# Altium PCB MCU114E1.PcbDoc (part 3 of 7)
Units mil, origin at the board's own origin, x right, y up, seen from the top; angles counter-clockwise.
Board outline 4163.97 x 2322.49 mil, 8 copper layers (Top Layer, GND 2, Signal Layer 3, Power 4, Power 5, Signal Layer 6, GND 7, Bottom), stack 61.2 mil thick; 444 components, 416 nets, 1812 pads, 989 vias.
Unrouted connection lines stored in the file: 3.
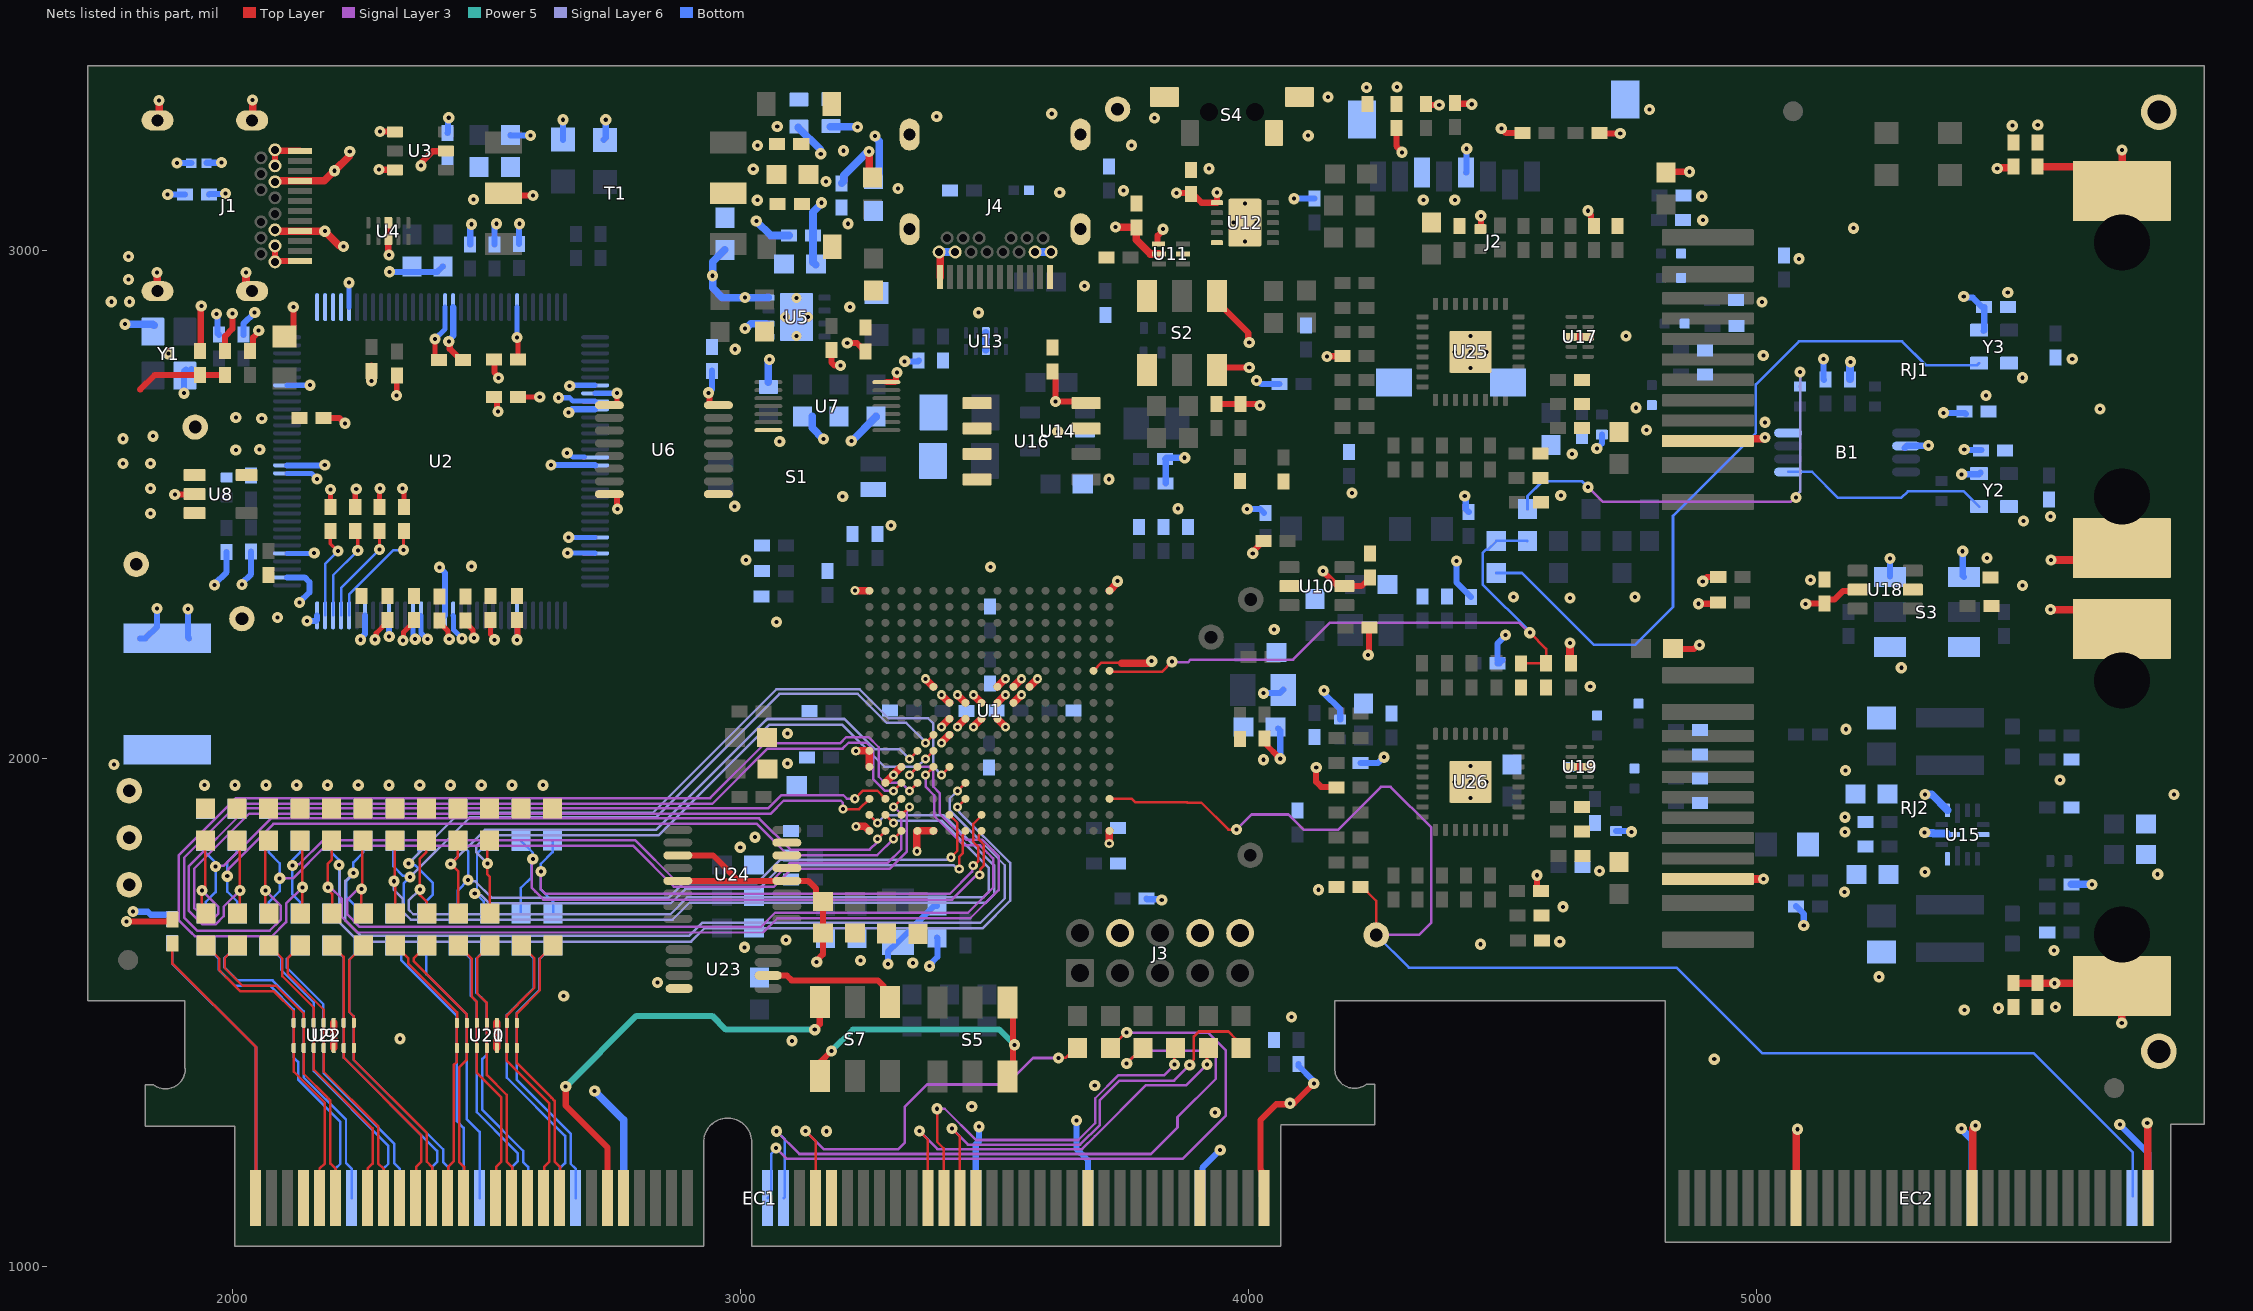
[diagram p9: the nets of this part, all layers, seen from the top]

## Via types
v1: diameter 22, hole 8, Top Layer to Bottom, tented both sides, 818 vias
v2: diameter 18, hole 8, Top Layer to Bottom, tented both sides, 153 vias
v3: diameter 19.68, hole 7.87, Top Layer to Bottom, 18 vias

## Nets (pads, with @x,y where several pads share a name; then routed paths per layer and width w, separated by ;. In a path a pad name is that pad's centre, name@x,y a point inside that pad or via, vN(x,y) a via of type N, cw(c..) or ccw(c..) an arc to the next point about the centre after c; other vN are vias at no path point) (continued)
3V3: B1.6 C31.1 C35.1 C36.1 C37.1 C40.2 C43.1 C64.1 C66.1 C86.2 C103.1 C152.1 C153.1 EC1.119 J2.4 J3.10 L3.1 L4.1 R1.2 R2.2 R34.1 R35.1 R36.2 R37.2 R39.2 R40.2 R42.2 R46.1 R51.2 R54.2 R71.2 R73.1 R88.2 R89.2 R105.2 R106.2 R107.2 R108.1 R111.2 R130.2 R131.1 R133.2 R134.2 R135.1 R137.2 R138.1 R142.1 R145.2 R151.2 R166.1 R168.2 R169.1 R194.2 R202.2 R204.2 R205.1 S2.1 S2.4 S3.1 S3.4 TP8.1 U6.16 U7.14 U10.5 U11.1 U12.1 U16.8 U18.5 Y2.4 Y3.4 | length 3588.3
  Top Layer w12: v1(1792,1680) 1872.2,1680 R204.2@1876.08,1683.88 ; v1(2937,2720) 2938.91,2718.09 2938.91,2697.42 2940.64,2695.69 U6.16@2956.44,2695.69 ; R1.2@3178.87,2800.13 3178.87,2779.69 3184.56,2774 v1(3197,2774) ; v1@3211,2818 3228.87,2818 C35.1@3245.68,2801.19 ; U7.14@3287.01,2740.93 3304.17,2740.93 3306.23,2742.99 3306.23,2758.67 v1(3307.83,2760.27) ; C86.2@3614,2761.57 3619.6,2755.96 v1(3619.6,2703.23) 3676.33,2703.23 U16.8@3679.87,2699.69 ; U11.1@3820.83,3014.5 3820.83,3029.13 3831,3039.29 v1(3831,3042) ; v1(3858,3113) 3888.38,3113 3907.32,3094.06 U12.1@3937.32,3094.06 3937.83,3094.57 v1(3937.83,3114.27) ; R54.2@3936.87,2698.31 R51.2@3983.87,2698.31 4018.69,2698.31 v1(4022,2695) v1@4023.31,2696.31 ; S2.4@3937.9,2765.17 3942.73,2770 v1(4001,2770) ; S2.1@3937.9,2910.83 3937.9,2899.02 3999.09,2837.83 3999.09,2820.91 v1(4001,2819) ; v1(4007.83,2404.27) 4007.83,2407.27 R39.2@4029.25,2428.69 ; EC1.119@4029.8,1135.27 4024.98,1140.09 4024.98,1189.44 4023,1191.42 4023,1289 4054.09,1320.09 4079.09,1320.09 v1(4081,1322) 4089,1322 v1(4128,1361) ; R46.1@4031,2039.38 4031,2031 v1(4062,2000) ; v1(4132.84,1982.84) 4132.67,1982.67 4132.67,1954.61 4142.6,1944.68 4172.26,1944.68 R142.1@4172.26,1942.8 ; v1(4145.83,2369.27) 4175.41,2339.69 U10.5@4188.01,2339.69 4221.87,2339.69 C37.1@4238.83,2356.65 ; v1(4153.83,2791.27) 4154.54,2791.98 4183.58,2791.98 R108.1@4184.29,2791.27 ; v1(4235,2204) 4236.45,2205.45 4236.45,2256.55 R40.2@4237.9,2258 ; C36.1@4290.4,3240.27 4290.4,3205.3 4301.83,3193.86 v1(4301.83,3193.27) ; R36.2@4348.51,3288.31 4350.55,3286.27 v1(4374.83,3286.27) ; R37.2@4406.83,3290.27 4408.23,3288.87 4437.77,3288.87 v1(4438.79,3287.85) ; R134.2@4455.83,3041.95 4456.67,3042.8 v1(4456.67,3068.27) ; v1(4497,3240) 4506,3231 R111.2@4538.38,3231 ; v1(4566.87,1770.69) 4566.87,1742.69 R151.2@4571.87,1737.69 ; v1(4667.83,3078.27) 4667.83,3075.56 4673.82,3069.57 4673.82,3051.9 R107.2@4677.83,3047.89 ; R89.2@4690.62,3231 4691.62,3230 v1(4731,3230) ; R135.1@4821.39,3153.32 4823.07,3155 v1(4867,3155) ; R169.1@4834.33,2217.27 4835.6,2216 4876.29,2216 4884.29,2224 v1(4887,2224) ; v1(4885,2305) 4920.57,2305 R138.1@4923.25,2307.69 ; v1(4893.28,2349.13) 4901.62,2357.48 R137.2@4923.6,2357.48 ; v1(5095.87,2304.69) 5096.87,2305.69 C103.1@5131.87,2305.69 ; C103.1@5132.44,2305.06 5132.44,2307.85 5138.25,2313.66 5152.85,2313.66 5169.2,2330.01 5196.2,2330.01 U18.5@5199.87,2333.69
  Bottom w12: v1(1804.5,1699.5) 1805,1699 1833.5,1699 1839.5,1693 1870.27,1693 1876.08,1687.19 R205.1@1876.08,1683.88 ; v1(2937,2720) 2944,2727 C31.1@2944,2763.38 ; v1(3290,1596) 3290,1620.27 3309,1639.27 L4.1@3309.83,1639.27 3381.33,1710.76 C66.1@3386.53,1710.76 ; v1(3323,2782) 3349.28,2782 R71.2@3350.58,2783.3 ; R202.2@3798.49,1724.69 3799.7,1723.48 3827.62,1723.48 v1(3828.83,1722.27) ; R105.2@3836.62,2542 3836.62,2589 R106.2@3835.62,2590 3837.82,2592.2 v1(3873.9,2592.2) ; v1(3996.87,2491.27) 4022.29,2491.27 R34.1@4030.06,2483.5 ; v1(4015.29,2744) 4018,2744 4025,2737 R88.2@4060.38,2737 ; v1(4029,2129) 4061.19,2129 L3.1@4067.87,2135.69 ; C64.1@4057.6,2059.54 4062,2055.14 v1(4062,2000) ; v1(4089,3102) 4128.38,3102 R194.2@4129,3102.62 ; R42.2@4098,1399.38 4098,1395.44 4126.09,1367.35 4126.09,1362.91 v1(4128,1361) ; v1(4148,2134) 4148,2129 4179.99,2097.01 R168.2@4179.99,2077.06 ; R130.2@4219.5,1991.68 4254.68,1991.68 v1(4266,2003) ; v1(4409,2389) 4409,2346.62 R145.2@4437,2318.62 ; v1(4425,2517) 4425,2514.29 4427.06,2512.23 4427.06,2491.12 R35.1@4432.87,2485.31 ; J2.4@4427.45,3153.27 4428.14,3153.96 4428.14,3199.58 v1(4428.83,3200.27) ; R133.2@4489.3,2187.89 4493.24,2187.89 4499.05,2193.7 4489.3,2193.7 4489.3,2226.59 4505,2242.29 v1(4505,2243.65) ; v1(4684.83,2610.27) 4694.83,2620.27 R131.1@4694.83,2637.58 ; R166.1@4722.83,1857.58 4751.52,1857.58 v1(4752.83,1856.27) ; R2.2@5077.15,1709.69 5092,1694.84 v1(5092,1672) ; v1(5130.87,2786.69) 5130.87,2746.69 R73.1@5131.87,2745.69 ; S3.4@5261.83,2358.64 v1(5261.83,2394.27) ; B1.6@5290.87,2611.69 5295.06,2615.87 5337.44,2615.87 v1(5337.83,2616.27) ; v1(5366.87,2680.69) 5408.87,2680.69 C43.1@5410.87,2678.69 ; v1(5402.87,2559.69) 5436.87,2559.69 Y2.4@5439.87,2562.69 ; v1(5404.83,2408.27) 5404.83,2360.02 S3.1@5407.27,2357.58 ; v1(5406.83,2909.27) 5408.74,2907.36 5424.58,2907.36 5443.25,2888.69 C153.1@5447.19,2888.69 ; v1(5407.83,2608.27) 5408.62,2607.48 5441.66,2607.48 C152.1@5441.87,2607.69 ; Y3.4@5445.87,2841.69 5447.19,2843 C153.1@5447.19,2887.69
  other v1: 3210.02,2818
5V0: C51.1 C53.1 C54.1 R20.2 R21.2 R28.2 R29.2 R53.2 R93.1 R99.2 R103.2 TP9.1 U11.2 U15.7 U15.11 | length 335.2
  Top Layer w15: v1@3738,3045.38 v1(3738,3046) 3738.25,3045.75 C51.1@3778.81,3045.75 3778.81,3020.93 3806.47,2993.27 U11.2@3823.17,2993.27
  Bottom w15: R20.2@3054.73,2740.93 3054.73,2783.65 v1(3056.88,2785.8) ; v1(3218,2624.98) 3219.01,2624.98 3266.55,2672.52 R21.2@3266.55,2673.5 ; v1(5330.83,1929.69) 5343.64,1929.69 U15.11@5374.91,1898.42 ; R103.2@5618.44,1752.69 v1(5659.44,1752.69)
  other v1: 5330.83,1777.27 5820.44,1929.69 3769,3207
20MHZ_CLK: R70.1 Y3.3 | length 1437.9
  Bottom w5.2: R70.1@4487,2365.5 4537.5,2365.5 4679,2224 4760,2224 4834.83,2298.83 4834.83,2477.83 4997.83,2640.83 4997.83,2736.27 5082.83,2821.27 5285.83,2821.27 5332.83,2774.27 5433.13,2774.27 Y3.3@5437.07,2778.21
25MHZ_CLK: B1.1 Y2.3 | length 414.8
  Bottom w5: B1.1@5061.29,2564.3 5108.8,2564.3 5159.83,2513.27 5283.83,2513.27 5296.83,2526.27 5407.01,2526.27 Y2.3@5437.07,2496.21
ADC_3V0_REF: S7.6 U23.6 | length 272.3
  Top Layer w12: U23.6@3054.43,1573.47 3091.2,1573.47 3100.83,1563.84 3270.19,1563.84 3280.81,1553.22 3280.81,1535.03 S7.6@3294.49,1521.35
ADC_REF: C123.1 R57.2 U24.3 U24.5 U24.12 | length 574
  Top Layer w12: U24.5@2876.55,1759.77 2995.83,1759.77 ; U24.3@2876.55,1809.77 2945.83,1809.77 2995.83,1759.77 ; v1(3149.83,1600.27) 3149.83,1602.97 3162.1,1615.24 C123.1@3162.1,1657.51 R57.2@3162.1,1719.51 3161.11,1719.51 3148.41,1732.21 3148.41,1744.9 3133.55,1759.77 U24.12@3091.11,1759.77 2995.83,1759.77
DEBUG_ID4: R3.1 U2.63 | length 183.1
  Top Layer w6.25: R3.1@2192.85,2448.01 2192.85,2422.89 2207.05,2408.69 v1(2207.87,2408.69)
  Bottom w5: U2.63@2182.5,2282.11 2182.5,2383.31 v1(2207.87,2408.69)
DEBUG_ID5: R4.1 U2.62 | length 193.1
  Top Layer w6.25: R4.1@2241.87,2448.06 2246.87,2443.06 v1(2246.87,2409.69)
  Bottom w5: U2.62@2198.25,2282.11 2198.25,2361.06 v1(2246.87,2409.69) ; v1@2248.37,2408.19 v1@2251.87,2411.69
DEBUG_ID6: R5.1 U2.61 | length 197.4
  Top Layer w6.25: v1(2289.87,2411.69) R5.1@2289.87,2448.06
  Bottom w5: U2.61@2214,2282.11 2214,2335.81 v1(2289.87,2411.69)
DEBUG_ID7: R6.1 U2.60 | length 222.5
  Top Layer w6.25: v1(2336.87,2410.69) 2336.87,2447.06 R6.1@2337.87,2448.06
  Bottom w5: U2.60@2229.74,2282.11 2229.74,2323.56 2316.87,2410.69 v1(2336.87,2410.69)
EMU_0: EC1.2 R205.2 | length 567
  Bottom w5: R205.2@1881.64,1637.31 1881.64,1597.36 2046.62,1432.38 EC1.2@2046.62,1138.69
EMU_1: EC1.1 R204.1 | length 566.1
  Top Layer w5: R204.1@1882,1636.63 1882,1597 2046.62,1432.38 2046.62,1282.29 EC1.1@2046.62,1138.69
EMU_3V3: C2.1 C3.1 C4.1 C5.1 C6.1 C7.1 C8.1 C9.1 C17.1 C30.1 R3.2 R4.2 R5.2 R6.2 R7.1 R10.2 R13.2 R14.1 TP2.1 U2.7 U2.8 U2.9 U2.16 U2.26 U2.28 U2.39 U2.47 U2.51 U2.52 U2.69 U2.79 U2.90 U2.101 U2.113 U2.122 U6.1 U8.5 | length 1528.1
  Top Layer w10: R3.2@2192.85,2495.26 v1(2192.87,2529.69) ; R4.2@2241.87,2495.31 2241.87,2528.69 v1(2243.87,2530.69) ; v1(2280.83,2234.27) 2283.13,2236.56 2283.13,2246.92 2305.09,2268.89 C7.1@2305.09,2272.82 ; R5.2@2289.87,2495.31 2289.87,2530.69 v1(2290.87,2531.69) ; v1(2323,2715) 2323.5,2715.5 2323.5,2753.88 R7.1@2324,2754.38 ; v1(2334.87,2531.69) 2337.87,2528.69 R6.2@2337.87,2495.31 ; v1(2335.98,2232.42) 2337.13,2233.56 2337.13,2249.33 2349.06,2261.27 2349.48,2261.27 2357.09,2268.89 C6.1@2357.09,2272.82 ; v1(2398.87,2825.69) 2398.87,2792.06 C9.1@2406.25,2784.69 ; C5.1@2408.09,2271.82 2408.09,2267.89 2424.54,2251.44 2424.54,2237.56 v1(2426.83,2235.27) ; C4.1@2459.09,2271.82 2459.09,2267.89 2473.54,2253.44 2473.54,2239.56 v1(2475.83,2237.27) ; C3.1@2508.09,2272.82 2508.09,2244.72 2519.09,2233.72 v1@2519.09,2233.07 ; v1(2559.87,2828.69) 2562.49,2826.06 C8.1@2562.49,2785.69 C8.1@2563.25,2786.44 ; C30.1@2560.87,2711.69 v1(2604.87,2711.69) ; U6.1@2741.87,2695.69 2754.18,2695.69 2756.83,2698.34 v1(2756.83,2719.27)
  Top Layer w12: R14.1@2034.87,2802.31 2040.68,2808.12 2040.68,2828.79 2051.87,2839.98 v1(2051.87,2842.69) ; C2.1@2560.09,2272.82 2561.09,2271.82 v1@2561.09,2234.44
  Bottom w10: U2.69@2107.7,2404.16 2160.18,2404.16 v1(2161.09,2405.07) ; U2.79@2107.7,2561.64 2155.92,2561.64 v1(2166.87,2550.69) ; U2.90@2107.7,2734.86 2107.8,2734.97 2152.99,2734.97 v1(2153.09,2735.07) ; U2.101@2229.74,2888.41 2229.74,2936.56 v1(2229.87,2936.69) ; U2.52@2355.73,2282.11 2355.73,2239.37 v1(2359.83,2235.27) ; U2.51@2371.48,2282.11 2371.48,2247.62 v1(2383.83,2235.27) ; v1@2397.87,2824.69 v1(2398.87,2825.69) 2418.72,2845.53 U2.113@2418.72,2888.41 ; U2.47@2434.47,2282.11 2435.53,2281.05 2435.53,2253.46 2451.83,2237.16 v1(2451.83,2236.27) ; v1(2559.87,2828.69) 2560.45,2829.27 U2.122@2560.45,2888.41 ; v1@2560.09,2233.07 2560.45,2233.42 U2.39@2560.45,2282.11 ; v1(2641.85,2710.32) 2663.7,2710.32 2670.4,2703.62 2714,2703.62 U2.9@2714,2703.37 ; v1(2658.87,2601.69) 2661.58,2601.69 2669.94,2593.32 U2.16@2692.44,2593.32 ; v1(2659.87,2404.69) 2713.47,2404.69 U2.28@2714,2404.16 ; v1(2661.87,2435.69) U2.26@2713.98,2435.67 ; v1(2663.83,2733.27) 2665.43,2734.86 U2.7@2714,2734.86 ; U2.8@2714,2719.12 2714.07,2719.19 2756.76,2719.19 v1(2756.83,2719.27)
  other v1: 2516.09,2234.07 2560.09,2234.07 2006.87,2607.69 2053.87,2608.69 2057.87,2669.69 2006.87,2671.69
EMU_GND: C1.2 C2.2 C3.2 C4.2 C5.2 C6.2 C7.2 C8.2 C9.2 C10.2 C11.2 C12.2 C13.2 C14.2 C15.2 C16.2 C17.2 C18.2 C19.2 C20.2 C21.1 C22.2 C30.2 C34.2 D2.1 D8.2 D13.2 J1.A1 J1.A12 J1.B1 J1.B12 J1.M1 J1.M2 J1.S1 J1.S2 J1.S3 J1.S4 R11.1 R12.1 R15.1 R16.1 R17.2 TP3.1 U2.10 U2.17 U2.48 U2.55 U2.58 U2.64 U2.66 U2.80 U2.114 U3.4 U3.6 U4.3@2306.85,3021.82 U4.8@2306.85,3054.7 U6.8 U8.2 Y1.2 Y1.4 | length 2515.9
  Top Layer w12: v1(1886.87,2519.69) 1887.37,2520.19 1925.37,2520.19 U8.2@1926.87,2521.69 ; C18.2@1936.87,2802.31 1937.94,2803.37 1937.94,2889.94 v1(1939,2891) ; C16.2@1985.87,2802.31 1985.87,2831.69 2000,2845.81 v1(2000,2876) ; J1.M1@2083.93,3009.26 J1.B1@2083.93,2977.76 2085.9,2979.73 J1.A12@2133.54,2979.73 ; J1.M2@2083.93,3166.74 J1.B12@2083.93,3198.24 2085.9,3196.27 J1.A1@2133.54,3196.27 ; D2.1@2102.87,2831.02 2104.35,2831.02 2120,2846.68 v1(2120,2889) ; C17.2@2179.49,2670.69 2210.35,2670.69 2221.04,2660 v1(2222,2660) ; v1(2273.87,2743.69) C1.2@2273.87,2773.69 ; v1(2288.83,3159.27) 2289.13,3158.97 2319.6,3158.97 U3.6@2319.9,3158.66 ; v1(2290.83,3234.27) 2291.23,3233.87 2319.5,3233.87 U3.4@2319.9,3233.47 ; U4.8@2306.85,3054.7 U4.3@2306.85,3021.82 2306.85,2992.31 v1(2308.09,2991.07) ; v1(2426,2821) 2427.91,2819.09 2427.91,2806.33 2449.56,2784.69 C9.2@2453.49,2784.69 ; C30.2@2515.25,2713.69 2520.92,2708.02 2520.92,2685.18 v1(2522.83,2683.27) ; C8.2@2515.25,2785.69 2515.87,2785.06 2515.87,2759.93 2523.83,2751.97 v1(2523.83,2749.27) ; U6.8@2741.87,2520.69 2755.48,2520.69 2757.21,2518.95 2757.21,2492.35 v1(2757.87,2491.69)
  Top Layer w15: v1(1852,2957) 1852,2920.72 J1.S3@1852.83,2919.89 ; J1.S2@1852.83,3256.11 1856,3259.28 v1(1856,3295) ; v1(2027,2957) 2027,2931.94 J1.S4@2039.05,2919.89 ; J1.S1@2039.05,3256.11 2040,3257.06 v1(2040,3296)
  Bottom w12: C34.2@1818.87,2236.69 1828.87,2236.69 1851.87,2259.69 v1(1851.87,2295.69) ; v1(1872.83,3110.27) 1872.93,3110.17 1906.37,3110.17 R15.1@1906.47,3110.07 ; v1(1890.83,3172.27) 1890.93,3172.17 1919.19,3172.17 C20.2@1919.29,3172.07 ; v1(1904.64,2719.27) 1904.64,2762.08 Y1.4@1908.83,2766.27 ; v1(1912.87,2294.69) 1912.87,2238.69 C34.2@1914.87,2236.69 ; Y1.4@1914.04,2761.05 Y1.4@1919.37,2766.38 ; v1(1964.87,2341.69) 1964.87,2343.18 1988.87,2367.18 C15.2@1988.87,2407.06 ; v1(1969,2875) 1970.91,2873.09 1970.91,2837.27 C14.2@1973.87,2834.31 ; v1(2018.87,2342.69) 2018.87,2345.39 2036.87,2363.39 R11.1@2036.87,2407.44 ; C13.2@2021.87,2834.31 2021.87,2855.87 v1(2044,2878) ; U2.66@2107.7,2356.91 2142.19,2356.91 2151.83,2347.27 2151.83,2327.64 v1(2131.87,2307.69) ; U2.80@2107.7,2577.38 2181.57,2577.38 v1(2181.87,2577.69) ; v1(2146.83,2271.27) 2164.69,2271.27 2166.75,2273.33 U2.64@2166.75,2282.11 ; v1(2252.33,2234.07) 2252.33,2236.88 2261.24,2245.78 U2.58@2261.24,2282.11 ; U2.55@2308.48,2282.11 2308.66,2281.94 v1(2308.66,2240.44) ; v1(2309.09,2958.07) 2403.59,2958.07 R17.2@2414.09,2968.57 ; v1(2407.53,2376.69) 2418.72,2365.5 U2.48@2418.72,2282.11 ; C22.2@2423.63,3231.17 2424.73,3232.28 2424.73,3260.17 v1(2425.83,3261.27) ; v1(2426,2821) 2426,2823.71 2434.73,2832.44 2434.73,2888.14 U2.114@2434.47,2888.41 ; C11.2@2468.09,3011.69 2468.09,3048.91 v1(2470.87,3051.69) ; C12.2@2516.09,3011.69 2516.09,3048.91 v1(2519.87,3052.69) ; C21.1@2547.09,3226.94 2547.77,3226.27 v1(2586.83,3226.27) ; C10.2@2564.09,3012.69 2564.09,3051.91 v1(2564.87,3052.69) ; v1(2626.83,2578.27) 2627.27,2577.83 2713.55,2577.83 U2.17@2714,2577.38 ; D8.2@2650.87,3218.02 2650.83,3218.07 v1(2650.83,3257.27) ; v1(2661.83,2681.27) 2668.18,2687.62 U2.10@2714,2687.62 ; D13.2@2730.87,3218.02 2734.83,3221.98 v1(2734.83,3257.27)
  Bottom w15: v1(1789,2855) 1843.72,2855 Y1.2@1845.84,2852.88
  other v1: 2088.87,2277.69 2470.87,2378.69
EMU_USB_5V0: C16.1 C18.1 C20.1 C21.2 C22.1 J1.A4 J1.A9 J1.B4 J1.B9 R15.2 R18.2 T1.5 TP1.1 U3.2 U8.1 U8.3 | length 692.2
  Top Layer w12: 1818.87,2726.69 1847.25,2755.06 C18.1@1936.87,2755.06 C16.1@1985.87,2755.06 ; v1(2201,3157) v1@2202,3158 ; v1@2368.86,3170.17 2372,3170.17 2373.36,3171.53 2373.36,3174.67 2394.08,3195.39 2419.61,3195.39 U3.2@2420.29,3196.07 ; T1.5@2533.61,3112.69 2538.03,3108.27 v1(2591.83,3108.27)
  Top Layer w15: J1.B4@2083.93,3040.76 2086.53,3038.16 2096.14,3038.16 2096.29,3038 2133.54,3038 v1(2182,3038) 2210.66,3009.34 2217.66,3009.34 v1(2219,3008) ; J1.B9@2083.93,3135.24 2085.9,3137.21 J1.A4@2133.54,3137.21 2181.21,3137.21 v1(2201,3157) ; v1@2202,3158 2229.66,3185.66 2229.66,3193.66 v1(2231,3195)
  Bottom w12: C20.1@1949.09,3172.07 1949.7,3172.67 1978.23,3172.67 v1(1978.83,3173.27) ; R15.2@1953.72,3110.07 1954.82,3111.17 1985.73,3111.17 v1(1986.83,3112.27)
  other v1: 1838.87,2482.69 1838.87,2531.69 1784.87,2580.69 1838.87,2580.69 1784.87,2629.69 1843.87,2634.69 1874,2797 1761.83,2899.27 1797.83,2899.27 1795.83,2943.27 1795.83,2988.27 2474.83,3100.27 2371.45,3166.91
ERRORSTS: EC2.178 R38.2 TP4.1 U1.P16 | length 2921.4
  Top Layer w5: U1.P16@3726.04,1921.06 3770.21,1921.06 3777.34,1913.94 3878.79,1913.94 3878.96,1913.77 3906.48,1913.77 3959.74,1860.52 v1(3975.88,1860.52) ; R38.2@4218.95,1752.27 4250.83,1720.39 TP4.1@4250.83,1653.27
  Signal Layer 3 w5: v1(3975.88,1860.52) 4005.63,1890.27 4078.04,1890.27 4108.3,1860 4175.29,1860 4260.06,1944.77 4279.08,1944.77 4359.3,1864.55 4359.3,1677.73 4334.83,1653.27 TP4.1@4250.83,1653.27
  Bottom w5: TP4.1@4250.83,1653.27 4315.1,1589 4842.01,1589 5010.25,1420.77 5544.23,1420.77 5739.14,1225.86 EC2.178@5739.14,1138.98
ETH1_EARTH: C101.2 C117.2 pad.6 R136.2 R170.2 RJ1.10 RJ1.13 RJ1.14 RJ2.10 RJ2.13 RJ2.14 | length 1047.5
  Top Layer w15: RJ2.10@4903.31,1763.48 5012.62,1763.48 v1(5012.83,1763.27) ; RJ1.10@4903.31,2625.13 4907.81,2629.64 5011.75,2629.64 5014.11,2632 v1(5016,2632) ; v1(5472.83,3161.27) 5474.17,3162.61 5501.98,3162.61 C101.2@5504.44,3165.06 ; C117.2@5504.44,1558.31 R170.2@5552.44,1558.31 v1(5585.83,1558.27) ; R136.2@5552.44,3165.06 RJ1.13@5669.68,3165.06 ; v1(5577.44,2293.43) 5679.66,2293.43 RJ2.13@5717.87,2255.21 ; v1(5578.44,2390.94) 5694.31,2390.94 RJ1.14@5717.87,2414.5 ; v1(5585.83,1558.27) 5707.64,1558.27 5717.83,1548.07 v1(5717.83,1480.27) ; RJ1.13@5717.87,3116.87 5718.44,3117.43 v1(5718.44,3197.69)
F28P65x_25MHZ_CLK: R65.2 R75.2 | length 865.8
  Signal Layer 3 w5: v1(4667.83,2534.27) 4696.65,2505.45 5065.57,2505.45 5074.12,2514 v1(5077,2514)
  Signal Layer 6 w5: v1(5077,2514) 5077,2517.6 5084.83,2525.43 v1(5084.83,2761.27)
  Bottom w5.2: R75.2@4548.44,2491.17 4548.56,2491.29 4548.56,2516.56 4578,2546 4656.1,2546 v1(4667.83,2534.27) ; R65.2@5084.44,2732.53 5084.83,2732.92 v1(5084.83,2761.27)
F28P65x_CLK: C126.1 R41.2 R70.2 R75.1 U1.F16 | length 1293.3
  Top Layer w5: U1.F16@3726.04,2173.03 3728.1,2170.97 3828.97,2170.97 v1(3849,2191) ; C126.1@4536,2187.62 4584.73,2187.62 R41.2@4585,2187.89 4585,2216 v1(4553,2248)
  Signal Layer 3 w5: v1(3849,2191) 3850.23,2189.77 3880.08,2189.77 3885.48,2195.17 4087.25,2195.17 4160.09,2268 4531.57,2268 4551.57,2248 v1(4553,2248)
  Bottom w5: R75.1@4548.44,2428.17 4548.11,2428.5 R70.2@4487,2428.5 4487,2427.51 4470.8,2411.31 4466.66,2411.31 4460.8,2405.45 4460.8,2342.2 4553,2250 v1(4553,2248)
GND: B1.4 C23.2 C24.2 C25.2 C26.2 C27.2 C28.2 C29.2 C31.2 C32.2 C33.2 C34.1 C35.2 C36.2 C37.2 C38.2 C39.2 C40.1 C41.2 C42.2 C43.2 C44.2 C45.2 C46.2 C47.2 C49.2 C51.2 C52.2 C53.2 C54.2 C55.2 C56.2 C57.2 C58.2 C59.2 C60.2 C61.2 C62.2 C63.2 C64.2 C65.2 C66.2 C67.2 C68.2 C69.2 C70.2 C71.2 C72.2 C73.2 C74.2 C75.2 C76.2 C77.2 C78.2 C79.2 C80.2 C81.2 C82.2 C83.2 C84.2 C85.2 C86.1 C87.1 C88.1 C89.2 C90.2 C91.2 C92.2 C93.2 C94.2 C95.1 C96.1 C97.2 C98.2 C99.2 C100.2 C101.1 C102.1 C103.2 C104.1 C105.2 C106.2 C107.2 C108.2 C109.2 C110.2 C111.1 C112.1 C113.2 C114.1 C115.2 C116.1 C117.1 C118.2 C119.2 C120.2 C121.2 C122.2 C123.2 C124.2 C125.2 C126.2 C128.2 C129.2 C130.2 C131.2 C132.2 C133.2 C134.2 C135.2 C136.2 C137.2 C138.2 C139.2 C140.2 C141.2 C142.2 C143.2 C144.2 C145.2 C146.2 C147.2 C148.2 C149.2 C150.2 C151.2 C152.2 C153.2 D7.1 D9.1 EC1.7 EC1.10 EC1.19 EC1.22 EC1.35 EC1.38 EC1.46 EC1.47 EC1.65 EC1.83 EC1.97 EC1.111 EC2.135 EC2.157 EC2.179 J2.6 J2.S1 J2.S2 J2.S3 J2.S4 J3.4 J3.8 J4.A1 J4.A12 J4.B1 J4.B12 J4.M1 J4.M2 J4.S1 J4.S2 J4.S3 J4.S4 R22.1 R23.1 R25.1 R26.1 R27.1 R31.1 R32.2 R38.1 R41.1 R43.1 R48.2 R69.1 R72.1 R74.2 R76.1 R77.1 R95.1 R104.1 R109.1 R112.1 R113.1 R123.1 R124.1 R125.1 R127.1 R128.1 R129.1 R132.1 R136.1 R139.2 R140.2 R141.2 R143.1 R146.1 R147.1 R159.1 R160.1 R161.1 R162.1 R163.2 R167.1 R170.1 R171.1 R206.1 S1.4 S2.3 S2.6 S3.3 S3.6 S4.1 S4.2 S4.3 T1.2 TP14.1 U1.A1 U1.A16 U1.F15 U1.G5 U1.G9 U1.G10 U1.G11 U1.H6 U1.H7 U1.H8 U1.H9 U1.H10 U1.J6 U1.J7 U1.J8 U1.J9 U1.K6 U1.L1 U1.M1 U1.M3 U1.N2 U1.T1 U1.T4 U1.T5 U1.T16 U5.5 U5.9@3110.34,2868.99 U6.9 U7.7 U9.5 U9.10 U10.2 U11.5 U12.5 U12.11 U13.3@3482.69,2805.13 U13.8@3482.69,2838 U14.2 U15.2 U15.9 U16.1 U16.2 U16.3 U16.4 U16.7 U17.3@4634.86,2830.21 U17.8@4667.74,2830.21 U18.2 U19.3@4634.86,1984.21 U19.8@4667.74,1984.21 U20.5 U20.10 U21.5 U21.10 U22.5 U22.10 U23.4 U24.13 U24.14 U24.15 U25.33@4436.44,2800.69 U26.33@4436.44,1954.69 Y2.2 Y3.2 | length 1781.7
  Top Layer w5: U1.F15@3694.54,2173.03 3710.52,2189 3750.17,2189 3751.63,2190.46
  Top Layer w15: U9.5@2199.56,1431.08 U9.10@2199.56,1480.29 ; U20.5@2520.56,1431.08 U20.10@2520.56,1480.29 ; v2(3225.5,2330.98) 3225.83,2330.65 3253.46,2330.65 U1.A1@3253.6,2330.51 ; v2(3226.84,2015.32) 3227.07,2015.55 U1.L1@3253.6,2015.55 U1.M1@3253.6,1984.05 ; v2(3227,1867) 3244.66,1867 U1.T1@3253.6,1858.07 ; U1.N2@3285.09,1952.55 v2(3300.84,1968.3) U1.M3@3316.59,1984.05 ; v2(3347,1818) 3347,1856.98 U1.T4@3348.09,1858.07 U1.T5@3379.58,1858.07 ; v2(3363.83,2157.28) U1.G5@3379.58,2141.53 ; J4.B1@3390.76,2997.07 3392.73,2995.1 J4.A12@3392.73,2947.46 ; v2@3394.16,2062.6 3395.14,2062.6 U1.J6@3411.08,2078.54 ; v2(3395.33,2031.29) U1.K6@3411.08,2047.04 ; v2(3395.33,2125.78) U1.H6@3411.08,2110.03 ; v2@3425.65,2062.6 3426.63,2062.6 U1.J7@3442.57,2078.54 ; v2(3426.83,2125.78) U1.H7@3442.57,2110.03 ; v2@3457.15,2062.6 3458.13,2062.6 U1.J8@3474.07,2078.54 ; v2(3458.32,2125.78) U1.H8@3474.07,2110.03 ; U1.J9@3505.57,2078.54 v2(3521.31,2062.79) ; U1.H9@3505.57,2110.03 v2(3521.31,2125.78) ; U1.G9@3505.57,2141.53 v2(3521.31,2157.28) ; U1.H10@3537.06,2110.03 v2(3552.81,2125.78) ; U1.G10@3537.06,2141.53 v2(3552.81,2157.28) ; U1.G11@3568.56,2141.53 v2(3584.31,2157.28) ; v2(3725.44,1832.95) 3725.44,1857.47 U1.T16@3726.04,1858.07 ; U1.A16@3726.04,2330.51 3726.04,2330.71 3740.32,2344.99 3740.32,2348.06 v1(3741.66,2349.39) ; 3750.17,2187.67 3804.67,2187.67 v1(3809,2192) ; v1(4632,2228) 4632,2189.72 R143.1@4633.83,2187.89 ; U19.3@4634.86,1984.21 U19.8@4667.74,1984.21 ; U17.3@4634.86,2830.21 U17.8@4667.74,2830.21 ; EC2.135@5076.95,1135.27 5076.95,1267.95 v1(5080,1271) ; EC2.157@5423.41,1135.27 5424.54,1136.4 5424.54,1272.54 v1(5430,1278) ; v1(5768,1283) 5768.93,1282.07 5768.93,1136.2 EC2.179@5769.87,1135.27
  Bottom w12: v1(3371.56,1591.75) 3371.56,1594.09 3387.56,1610.09 3387.56,1646.74 C66.2@3386.53,1647.77
  Bottom w15: v1(3031,3058) 3059.31,3029.69 C29.2@3095.25,3029.69 ; 3140.78,2673.5 3140.78,2651.22 v1(3163,2629) ; J4.B1@3390.76,2997.07 J4.M1@3422.26,2997.07 ; U13.3@3482.69,2805.13 U13.8@3482.69,2838 ; J4.M2@3579.74,2997.07 J4.B12@3611.24,2997.07 ; R74.2@5183,2746.62 5183,2780 v1(5184,2781) ; v1(5330,1855) 5331.08,1853.92 5346.29,1853.92 5347.26,1852.95 5373.14,1852.95 U15.9@5375.4,1850.69
  other v1: 3169,1267 3934,1304 3455,1316 3697,1357 4916,1408.86 3101,1445 2330,1449 4084,1492 5408,1505.86 5475,1509 5587.44,1511.69 2652,1533 2836.44,1559.69 5240.27,1570.95 3339,1598 3236,1603 5584.44,1622.69 3008,1629 4456,1635 4612,1640 3089.27,1643.42 4618.44,1708.69 5172.44,1737.69 4137.44,1742.24 5788.44,1772.69 4690,1779 2999.44,1825.69 3028.44,1845.69 5173,1856 5173,1885 1945,1948 2005.55,1948 2066.09,1948 2126.64,1948 2187.18,1948 2247.73,1948 2308.27,1948 2368.82,1948 2429.36,1948 2489.91,1948 2550.45,1948 2611,1948 5596,1958 5174.44,1976.69 1767,1988.75 3092.44,1990.69 4029,1998 3092.44,2049.69 5175,2058 4672,2142 5284,2179 4050,2254 3071,2269 4632,2316 4521,2318 4760,2318 5522.44,2340.69 5105.44,2351.69 3492,2377 3011,2391 5452.44,2394.69 3295.77,2458.95 5524.44,2467.69 5577.44,2476.69 3861,2492 2988.44,2496.69 3201,2516 4614,2518 4203,2523 3725,2550 4636.44,2599.69 3077,2624 3624.31,2644 4782.44,2646.69 5016,2662 5675,2688 4762.1,2690.64 5450.44,2714.69 5522.44,2749.69 5620.44,2786.69 5012.44,2793.69 2989.44,2805.69 4742,2832 3468.28,2877.64 3215,2889 5010.07,2898.78 5493.44,2917.69 3677,2930 5082.44,2983.69 5190,3044 3211.44,3052.69 4893.44,3059.69 3033,3099 4343.44,3099.69 4405.44,3099.69 4891.44,3106.69 3628,3114 3753.44,3117.69 3310,3122 3025,3160 3922,3161 3033.44,3206.69 4117,3226 3072.27,3243.95 5502.44,3245.69 5552.44,3246.69 3814.44,3260.69 3386,3264 3612.34,3269.11 4788.44,3277.69 4156,3302 4231.44,3320.69 4291.44,3321.69
  other v2: 3395.33,2062.79 3426.83,2062.79 3458.32,2062.79
  other v3: 4436.44,1923.19 4404.94,1954.69 4436.44,1954.69 4467.93,1954.69 4436.44,1986.18 4436.44,2769.19 4404.94,2800.69 4436.44,2800.69 4467.93,2800.69 3110.34,2831.59 4436.44,2832.18 3087.7,2868.99 3132.97,2868.99 3110.34,2906.39 3992.44,3017.28 3969.8,3054.69 4015.07,3054.69 3992.44,3092.09
HSEC_5V0: C27.1 C28.1 EC1.48 EC1.84 EC1.98 EC1.112 EC2.158 EC2.180 R22.2 R24.2 R28.1 TP11.1 U5.8 | length 1437
  Top Layer w15: v1(3252.96,3194.58) 3252.96,3150.54 R24.2@3260,3143.5
  Bottom w12: EC1.84@3462.87,1139.75 3462.87,1241 3468.87,1247 3468.87,1275.87 v1(3469,1276) ; v1(3661,1288) 3660.83,1287.83 3660.83,1232.95 3683.35,1210.43 EC1.98@3683.35,1135.27 ; EC1.112@3903.82,1135.27 3908.65,1140.09 3908.65,1195.08 v1(3943.83,1230.27) ; v1(5714,1280) 5738.34,1255.66 5769.87,1224.13 EC2.180@5769.87,1139.76
  Bottom w15: v1(2713,1346) 2769.96,1289.04 EC1.48@2769.96,1135.27 ; R22.2@2969,3001.5 2945.04,2977.55 v1(2945.04,2950.42) 2945.04,2926.52 2964.29,2907.27 v1(3009.02,2907.27) U5.8@3053.75,2907.27 ; U5.8@3053.75,2907.69 U5.8@3054.87,2907.69 ; R28.1@3176.83,3243.77 3177.08,3243.52 3229.58,3243.52 v1(3229.83,3243.27) ; C27.1@3198.87,3132.31 3203.18,3136.62 3203.18,3147.62 v1@3246.83,3191.27 ; C28.1@3261.87,3141.18 3273.07,3152.38 3273.07,3215.13 3264.83,3223.37 v1(3264.83,3225.27) ; v1@5401.83,1272.27 5423.41,1250.69 EC2.158@5423.41,1135.27
  other v1: 5402.04,1272.27
HSEC_ADC-VREFHI: EC1.45 S7.4 | length 871.6
  Top Layer w12: v1(2656,1355) 2656,1317.36 2724.18,1249.18 2738.46,1234.89 EC1.45@2738.46,1135.27 ; v1(3146,1466.91) 3146,1467.82 3155.83,1477.65 3155.83,1520.48 S7.4@3156.7,1521.35
  Power 5 w12: v1(2656,1355) 2795,1494 2944,1494 2971.09,1466.91 v1(3146,1466.91)
HSEC_ADC_A0A1_N: EC1.11 R176.2 U9.2 U9.13 | length 636.9
  Top Layer w4.9: R176.2@2010.13,1632.95 1985.08,1607.91 1985.08,1588.5 2002.81,1570.78 2020.59,1553 2086.45,1553 2140.5,1498.95 U9.13@2140.5,1480.29 2140.5,1380.1 2186.34,1334.26 2186.34,1334.19 2189.79,1330.74 2189.79,1330.67 2192.9,1327.56 2192.9,1203.52 2203.03,1193.39 EC1.11@2203.03,1135.27
HSEC_ADC_A0A1_P: EC1.9 R175.2 U9.1 U9.14 | length 637.6
  Top Layer w4.9: R175.2@1948.04,1632.95 1974.18,1606.81 1974.18,1583.99 1977.2,1580.97 1977.2,1580.83 1995.03,1563 1995.17,1563 2016.07,1542.1 2081.94,1542.1 2120.82,1503.22 U9.14@2120.82,1480.29 U9.1@2120.82,1431.08 2120.82,1384.3 2132.79,1372.32 2132.79,1372.25 2182,1323.04 2182,1203.85 2171.54,1193.39 EC1.9@2171.54,1135.27
HSEC_ADC_A2A3_N: EC1.17 R178.2 U9.4 U9.11 | length 586.1
  Top Layer w4.9: R178.2@2134.31,1632.95 2109.17,1607.82 2109.17,1576.83 2179.87,1506.13 U9.4@2179.87,1431.08 2179.87,1396.41 2179.87,1384.13 2287,1277 2287,1203.91 2297.52,1193.39 EC1.17@2297.52,1135.27
HSEC_ADC_A2A3_P: EC1.15 R177.2 U9.3 U9.12 | length 586.3
  Top Layer w4.9: R177.2@2072.04,1632.95 2098.27,1606.72 2098.27,1572.31 2160.19,1510.4 U9.3@2160.19,1431.08 2160.19,1388.26 2276,1272.44 2276,1203.36 2266.02,1193.39 EC1.15@2266.02,1135.27
HSEC_ADC_A4A5_N: EC1.23 R180.2 U9.7 U9.8 | length 572.5
  Top Layer w4.9: R180.2@2258.49,1631.97 2230.14,1603.62 2230.14,1501.92 2238.67,1493.39 2238.67,1480.55 U9.8@2238.93,1480.29 U9.7@2238.93,1431.08 2238.93,1407.49 2382.9,1263.52 2382.9,1207.03 2393.08,1196.85 EC1.23@2393.08,1138.69
HSEC_ADC_A4A5_P: EC1.21 R179.2 U9.6 U9.9 | length 571.3
  Top Layer w4.9: R179.2@2196.4,1632.95 2219.24,1610.11 U9.9@2219.24,1480.29 U9.6@2219.24,1431.08 2219.24,1411.76 2372,1259 2372,1207.27 2361.58,1196.85 EC1.21@2361.58,1138.69
HSEC_ADC_A8A9_N: EC1.36 R182.2 U21.4 U21.11 | length 554.5
  Bottom w4.9: R182.2@2505.87,1632.33 2505.87,1631.35 2489.62,1615.1 2488.64,1615.1 2480,1606.46 2480,1540 2489.74,1530.26 2500.62,1519.39 2500.62,1480.55 U21.4@2500.87,1480.29 U21.11@2500.87,1431.08 2500.87,1418.24 2492.09,1409.45 2492.09,1308.87 2572.31,1228.65 2572.31,1206.55 2582.05,1196.8 EC1.36@2582.05,1138.69
HSEC_ADC_A8A9_P: EC1.34 R181.2 U21.3 U21.12 | length 546.9
  Bottom w4.9: R181.2@2443.78,1632.33 2443.78,1631.35 2469.1,1606.03 2469.1,1533.79 2481.19,1521.7 U21.3@2481.19,1480.29 U21.12@2481.19,1431.08 2481.19,1304.36 2550.19,1235.36 2561.41,1224.14 2561.41,1207.65 2550.56,1196.8 EC1.34@2550.56,1138.69
HSEC_ADC_A10A11_N: EC1.42 R184.2 U21.7 U21.8 | length 575
  Bottom w4.9: R184.2@2631.04,1632.95 2604.4,1606.31 2604.4,1544.95 2559.93,1500.48 U21.7@2559.93,1480.29 U21.8@2559.93,1431.08 2559.93,1368.07 2665.73,1262.27 2665.73,1203.13 2675.47,1193.39 EC1.42@2675.47,1135.27
HSEC_ADC_A10A11_P: EC1.40 R183.2 U21.6 U21.9 | length 581.7
  Bottom w4.9: R183.2@2567.96,1632.33 2593.5,1606.79 2593.5,1549.47 2540.24,1496.21 U21.6@2540.24,1480.29 U21.9@2540.24,1431.08 2540.24,1372.34 2654.83,1257.75 2654.83,1204.24 2643.98,1193.39 EC1.40@2643.98,1135.27
HSEC_ADC_A14B14C14A15B15C15_N: EC1.27 R186.2 U20.2 U20.13 | length 559
  Top Layer w4.9: R186.2@2382.67,1632.95 2382.67,1631.97 2366.42,1615.72 2365.44,1615.72 2357.36,1607.64 2357.36,1601.03 2461.5,1496.89 U20.13@2461.5,1480.29 U20.2@2461.5,1431.08 2461.5,1407.95 2446.12,1392.57 2446.12,1206.8 2456.07,1196.85 EC1.27@2456.07,1138.69
HSEC_ADC_A14B14C14A15B15C15_P: EC1.25 R185.2 U20.1 U20.14 | length 552.5
  Top Layer w4.9: R185.2@2320.58,1632.95 2320.58,1631.97 2336.83,1615.72 2337.82,1615.72 2346.46,1607.07 2346.46,1596.51 2442.15,1500.82 2442.15,1480.63 U20.14@2441.82,1480.29 U20.1@2441.82,1431.08 2441.82,1403.68 2435.22,1397.08 2435.22,1207.5 2424.57,1196.85 EC1.25@2424.57,1138.69
HSEC_ADC_B0B1_N: EC1.14 R189.2 U22.2 U22.13 | length 653.4
  Bottom w4.9: R189.2@2010.13,1632.95 2010.13,1631.97 1994.43,1616.27 1993.44,1616.27 1983.98,1606.81 1983.98,1590.15 2010.23,1563.9 2079.39,1563.9 2140.5,1502.79 U22.2@2140.5,1480.29 U22.13@2140.5,1431.08 2140.5,1373.02 2223.68,1289.85 2223.68,1204.23 2234.53,1193.39 EC1.14@2234.53,1135.27
HSEC_ADC_B0B1_P: EC1.12 R188.2 U22.1 U22.14 | length 649.9
  Bottom w4.9: R188.2@1948.04,1632.95 1948.04,1631.97 1973.08,1606.92 1973.08,1585.63 2005.71,1553 2074.88,1553 2120.82,1507.06 U22.1@2120.82,1480.29 ; U22.1@2120.82,1478.26 U22.14@2120.82,1431.08 2120.82,1412.44 2129.6,1403.65 2129.6,1368.51 2212.78,1285.33 2212.78,1203.13 2203.03,1193.39 EC1.12@2203.03,1135.27
HSEC_ADC_B2B3_N: EC1.20 R191.2 U22.4 U22.11 | length 599.8
  Bottom w4.9: R191.2@2133.33,1632.33 2107.18,1606.18 2107.18,1589.11 2178.94,1517.36 2178.94,1487.13 2179.87,1486.2 U22.4@2179.87,1480.29 U22.11@2179.87,1431.08 2179.87,1380.89 2318.17,1242.6 2318.17,1204.23 2329.02,1193.39 EC1.20@2329.02,1135.27
HSEC_ADC_B2B3_P: EC1.18 R190.2 U22.3 U22.12 | length 598.9
  Bottom w4.9: R190.2@2071.23,1632.33 2096.28,1607.28 2096.28,1584.6 2160.19,1520.69 U22.3@2160.19,1480.29 U22.12@2160.19,1431.08 2160.19,1385.16 2307.27,1238.08 2307.27,1203.13 2297.52,1193.39 EC1.18@2297.52,1135.27
HSEC_ADC_B4B5_N: EC1.26 R193.2 U22.7 U22.8 | length 586.1
  Bottom w4.9: R193.2@2257.51,1632.33 2257.51,1631.35 2241.81,1615.65 2240.82,1615.65 2230.14,1604.97 2230.14,1501.92 2238.67,1493.39 2238.67,1480.55 U22.7@2238.93,1480.29 U22.8@2238.93,1431.08 2238.93,1407.49 2414.83,1231.59 2414.83,1206.55 2424.57,1196.8 EC1.26@2424.57,1138.69
HSEC_ADC_B4B5_P: EC1.24 R192.2 U22.6 U22.9 | length 584.2
  Bottom w4.9: R192.2@2195.42,1632.33 2195.42,1631.35 2211.12,1615.65 2212.1,1615.65 2219.24,1608.5 U22.6@2219.24,1480.29 U22.9@2219.24,1431.08 2219.24,1411.76 2402.83,1228.18 2402.83,1206.55 2393.08,1196.8 EC1.24@2393.08,1138.69
HSEC_ADC_C2C3_N: EC1.33 R196.2 U20.4 U20.11 | length 533.1
  Top Layer w4.9: U20.4@2500.87,1431.08 U20.11@2500.87,1480.29 2500.87,1519.13 2481.86,1538.14 2481.86,1607.96 R196.2@2506.85,1632.95 ; U20.4@2500.91,1431.04 2500.91,1377.51 2539.66,1338.76 2539.66,1317.34 2539.76,1317.24 2539.76,1207.65 2550.56,1196.85 EC1.33@2550.56,1138.69
HSEC_ADC_C2C3_P: EC1.31 R195.2 U20.3 U20.12 | length 533.1
  Top Layer w4.9: R195.2@2444.76,1632.95 2470.96,1606.76 2470.96,1533.63 2471,1533.59 2471,1531.89 2481.19,1521.7 U20.12@2481.19,1480.29 2481.19,1381.81 2528.76,1334.24 2528.76,1206.55 2519.06,1196.85 EC1.31@2519.06,1138.69
HSEC_ADC_C4: EC1.30 R197.2 U21.2 U21.13 | length 540.5
  Bottom w5: R197.2@2381.69,1632.33 2381.69,1576.31 2461.5,1496.5 U21.13@2461.5,1431.08 2461.5,1290.5 2486.5,1265.5 EC1.30@2486.5,1135.27
HSEC_ADC_C6: EC1.28 R201.2 U21.1 U21.14 | length 553.1
  Bottom w5: R201.2@2319.6,1632.33 2332.84,1619.09 2332.84,1603.16 2441.82,1494.18 U21.14@2441.82,1431.08 2441.82,1287 2455,1273.82 EC1.28@2455,1135.27
HSEC_ADC_C10C11_N: EC1.39 R173.2 U20.7 U20.8 | length 559
  Top Layer w4.9: R173.2@2631.04,1632.95 2605,1606.92 2605,1544 2559.93,1498.93 U20.8@2559.93,1480.29 U20.7@2559.93,1431.08 2559.93,1401.14 2627.73,1333.34 2627.8,1333.34 2634.25,1326.89 2634.25,1207.65 2645.05,1196.85 EC1.39@2645.05,1138.69
HSEC_ADC_C10C11_P: EC1.37 R172.2 U20.6 U20.9 | length 565.5
  Top Layer w4.9: R172.2@2568.95,1632.95 2594.1,1607.8 2594.1,1548.91 2572.35,1527.17 2552.15,1506.96 2540.24,1495.06 U20.9@2540.24,1480.29 2540.24,1405.41 2623.35,1322.31 2623.35,1206.65 2613.55,1196.85 EC1.37@2613.55,1138.69
HSEC_GPIO11: EC1.63 R96.1 | length 817
  Top Layer w5: v1(3127.83,1267.27) 3148.33,1246.77 3148.33,1135.69 EC1.63@3147.91,1135.27 ; v1(3625.83,1411.27) 3626.62,1412.05 3640.29,1412.05 R96.1@3663.44,1435.2
  Signal Layer 3 w5: v1(3127.83,1267.27) 3128.08,1267.27 3164.08,1231.27 3309.9,1231.27 3322.83,1244.2 3322.83,1314.73 3367.1,1359 3523.44,1359 3575.62,1411.19 3625.75,1411.19 v1(3625.83,1411.27)
HSEC_GPIO12: EC1.58 R45.2 | length 1416.6
  Top Layer w5: R45.2@3727.66,1430.77 3758.16,1461.27 v1(3759.83,1461.27)
  Signal Layer 3 w5: v1(3069.63,1233.76) 3090.12,1213.27 3870.27,1213.27 3955,1298 3955,1425.83 3919.56,1461.27 v1(3759.83,1461.27)
  Bottom w5: EC1.58@3053.43,1135.27 3060,1141.84 3060,1222.33 3069.63,1231.96 v1(3069.63,1233.76)
HSEC_GPIO13: EC1.60 R47.2 | length 1378.1
  Top Layer w5: v1(3759.83,1400.27) 3789.83,1430.27 3789.83,1434.06 R47.2@3791.96,1436.19
  Signal Layer 3 w5: v1(3071,1267) 3115.73,1222.27 3807.58,1222.27 3859.83,1274.52 3859.83,1294.83 3935.33,1370.33 3935.33,1412.77 3922.83,1425.27 3784.83,1425.27 v1(3759.83,1400.27)
  Bottom w5: v1(3071,1267) 3087.13,1250.87 3087.13,1137.48 EC1.60@3084.92,1135.27
HSEC_GPIO25: EC1.77 R98.1 | length 827.6
  Top Layer w5: v1(3351.83,1267.27) 3368.39,1250.71 EC1.77@3368.39,1135.27 ; v1(3917.83,1398.27) 3917.83,1433.41 R98.1@3920.61,1436.19
  Signal Layer 3 w5: v1(3351.83,1267.27) 3387.33,1231.77 3671.95,1231.77 3697,1256.82 3797.95,1357.77 3877.33,1357.77 v1(3917.83,1398.27)
HSEC_GPIO26: EC1.79 R50.2 | length 803.3
  Top Layer w5: v1(3386.83,1311.27) 3386.83,1246.3 3399.88,1233.25 EC1.79@3399.88,1135.27 ; R50.2@3849.6,1430.77 R50.2@3853.41,1426.95 ; v1(3853.83,1398.27) 3853.83,1428.36 R50.2@3856.25,1430.77
  Signal Layer 3 w5: v1(3386.83,1311.27) 3401.83,1311.27 3463.33,1249.77 3664.5,1249.77 3698,1283.27 3698,1332 3743,1377 3833.39,1377 3853.83,1397.44 v1(3853.83,1398.27)
HSEC_GPIO27: EC1.81 R56.2 | length 882.4
  Top Layer w5: v1(3415.83,1272.27) 3431.38,1256.72 EC1.81@3431.38,1135.27 ; v1(3883.83,1397.27) 3883.83,1400.47 3892.06,1408.7 3892.06,1453.5 3901.83,1463.27 3959.83,1463.27 3974.44,1448.66 R56.2@3974.44,1436.19
  Signal Layer 3 w5: v1(3415.83,1272.27) 3447.33,1240.77 3668.22,1240.77 3707,1279.54 3707,1328.27 3745.5,1366.77 3853.33,1366.77 v1(3883.83,1397.27)
"Int. V_REF": S5.1 S5.4 S7.1 | length 603
  Top Layer w12: S7.1@3156.7,1375.68 3156.7,1402.7 v1(3179,1425) ; S5.4@3525.49,1374.68 3536,1385.18 3536,1509.84 S5.1@3525.49,1520.35
  Power 5 w12: v1(3179,1425) 3221.27,1467.27 3508.89,1467.27 v1(3539.06,1437.1)
ISO_Pout_5V0: C23.1 C24.1 C25.1 C29.1 D3.1 D4.1 R23.2 R29.1 U5.6 | length 248.3
  Bottom w15: v1(3008.83,2846.27) 3010.73,2846.27 3020.54,2856.09 U5.6@3050.91,2856.09 ; R29.1@3113.83,3242.77 3113.83,3241.79 3156.49,3199.13 3156.49,3191.61 v1(3157.83,3190.27) ; R23.2@3147.87,2971.69 3142.49,2977.06 3142.49,3075.6 3159,3092.11 v1(3159,3094)
  other v1: 3167.87,3135.69 3202.83,3196.27
ITCK: U2.100
ITDI: U2.98
ITDO: U2.97
ITMS: U2.99
MCU_A0A1_N: C128.1 R176.1 U1.P2 | length 1830.9
  Top Layer w4.9: C128.1@2009.15,1839.38 2015.06,1833.47 v1(2015.06,1740.88) 2015.06,1700.88 R176.1@2010.13,1695.94 ; v2(3224.83,1921.27) 3240.74,1937.18 3268.97,1937.18 U1.P2@3285.09,1921.06
  Signal Layer 3 w4.9: v1(2015.06,1740.88) 1983.06,1708.88 1983.06,1690.47 1966.7,1674.1 1941.49,1674.1 1914.1,1701.49 1914.1,1788.27 2028.45,1902.62 3044.86,1902.62 3045.05,1902.43 3054.32,1902.43 3080.36,1928.47 3089.47,1928.47 3089.52,1928.42 3193.1,1928.42 3193.15,1928.37 3202.12,1928.37 3209.22,1921.27 v2(3224.83,1921.27)
MCU_A0A1_P: C140.1 R175.1 U1.P1 | length 1752.8
  Top Layer w4.9: C140.1@1947.06,1839.38 1947.06,1747.88 v1(1940.06,1740.88) 1940.06,1703.92 R175.1@1948.04,1695.94 ; v2(3201.83,1901.27) 3202.32,1900.78 3233.32,1900.78 U1.P1@3253.6,1921.06
  Signal Layer 3 w4.9: v1(1940.06,1740.88) 1972.06,1708.88 1972.06,1694.88 1962.18,1685 1946,1685 1925,1706 1925,1783.75 2032.97,1891.72 3040.34,1891.72 3040.53,1891.53 3058.84,1891.53 3084.72,1917.42 3188.54,1917.42 3188.59,1917.37 3197.56,1917.37 3201.08,1913.84 3201.08,1902.01 v2(3201.83,1901.27)
MCU_A2A3_N: C129.1 R178.1 U1.N4 | length 2226.6
  Top Layer w4.9: C129.1@2133.34,1839.38 2138,1834.72 v1(2138,1747) 2138,1699.63 R178.1@2134.31,1695.94
  Top Layer w5: v2(3332.34,1936.81) U1.N4@3348.09,1952.55
  Signal Layer 3 w4.9: v1(2138,1747) 2105.9,1714.9 2105.9,1678.49 2078.16,1650.75 2055.78,1650.75 2055.68,1650.65 1926.21,1650.65 1919.77,1657.09 1919.77,1657.24 1894.3,1682.71 1894.3,1809.71 2007,1922.42 2940.2,1922.42 3048.58,2030.8 3196.39,2030.8 3207.97,2042.38 3252.03,2042.38 3271.9,2022.51 3271.9,1964.52 3284.11,1952.31 3316.84,1952.31 v2(3332.34,1936.81)
MCU_A2A3_P: C141.1 R177.1 U1.N3 | length 2131.3
  Top Layer w4.9: C141.1@2071.24,1839.38 2065.06,1833.2 v1(2065.06,1740.88) 2065.06,1702.92 R177.1@2072.04,1695.94
  Top Layer w5: v2(3300.84,1936.81) U1.N3@3316.59,1952.55
  Signal Layer 3 w4.9: v1(2065.06,1740.88) 2095,1710.94 2095,1683 2073.65,1661.65 1930.77,1661.65 1930.77,1661.72 1930.71,1661.72 1905.2,1687.23 1905.2,1805.2 2011.52,1911.52 2944.71,1911.52 3053.1,2019.9 3200.9,2019.9 3212.48,2031.48 3247.52,2031.48 3261,2018 3261,1960 3284.19,1936.81 v2(3300.84,1936.81)
MCU_A4A5_N: C130.1 R180.1 U1.M5 | length 1845.9
  Top Layer w4.9: C130.1@2257.52,1839.38 2254,1835.86 2255.56,1835.86 2255.56,1745.56 v1(2254,1744) 2254,1700.44 R180.1@2258.49,1695.94
  Top Layer w5: v2(3363.83,1968.3) U1.M5@3379.58,1984.05
  Signal Layer 3 w4.9: v1(2254,1744) 2247.13,1744 2226.41,1723.28 2226.41,1693.18 2250.59,1669 3040,1669 3067.95,1696.95 3447.55,1696.95 3496.8,1746.21 3496.8,1804.04 3485.9,1814.94 3485.9,1815.08 3471.34,1829.65 3439.13,1829.65 3380.93,1887.85 3380.93,1928.07 3363.98,1945.02 v2@3363.98,1968.3
MCU_A4A5_P: C142.1 R179.1 U1.M4 | length 1946.6
  Top Layer w4.9: C142.1@2195.43,1839.38 2195.43,1800.99 2188,1793.56 v1(2188,1747) 2188,1742.4 2196.4,1734 R179.1@2196.4,1695.94
  Top Layer w5: v2(3332.34,1968.3) U1.M4@3348.09,1984.05
  Signal Layer 3 w4.9: v1(2188,1747) 2192.85,1747 2215.41,1724.44 2215.41,1688.76 2246.08,1658.1 3044.51,1658.1 3072.47,1686.05 3452.06,1686.05 3507.7,1741.7 3507.7,1808.55 3496.8,1819.45 3496.8,1819.6 3475.85,1840.55 3443.65,1840.55 3391.83,1892.36 3391.83,1932.58 3379.28,1945.13 3379.28,1974.7 3374.73,1979.25 3374.73,1979.32 3370.25,1983.8 3347.84,1983.8 v2(3332.34,1968.3)
MCU_A8A9_N: C131.1 R182.1 U1.T7 | length 1244.5
  Top Layer w4.9: v2(3430.33,1782.92) 3430.63,1783.22 3430.63,1807.46 3437.35,1814.18 3437.35,1849.91 3442.57,1855.13 U1.T7@3442.57,1858.07
  Signal Layer 6 w4.9: v1(2477,1735) 2480.27,1731.73 2489.61,1731.73 2506.15,1715.18 2862.66,1715.18 2891.37,1743.89 3036.3,1743.89 3083.04,1790.63 3419.08,1790.63 3426.79,1782.92 v2(3430.33,1782.92)
  Bottom w4.9: v1(2477,1735) v1@2479.23,1737.23 ; R182.1@2505.87,1695.32 2494.75,1706.45 2494.75,1719.49 2479.23,1735 v1@2479.23,1737.23 ; C131.1@2505.9,1838.38 2481.44,1813.92 2481.44,1739.44 v1@2479.23,1737.23
MCU_A8A9_P: C143.1 R181.1 U1.R6 | length 1252.4
  Top Layer w4.9: U1.R6@3411.08,1889.56 3426.45,1874.19 3426.45,1818.7 v2(3413.83,1806.08)
  Signal Layer 6 w4.9: v1(2463.94,1761.12) 2466.17,1758.89 2477.86,1758.89 2510.67,1726.08 2858.15,1726.08 2883.66,1751.6 2886.85,1754.79 3031.79,1754.79 3078.53,1801.53 3405.74,1801.53 3410.29,1806.08 v2(3413.83,1806.08)
  Bottom w4.9: R181.1@2443.78,1695.32 2443.78,1740.97 v1(2463.94,1761.12) 2463.94,1818.25 C143.1@2443.81,1838.38
MCU_A10A11_N: C132.1 R184.1 U1.R8 | length 1196.4
  Top Layer w4.9: v2(3457.83,1790.27) 3459.31,1790.27 3468.1,1799.06 3468.1,1826.17 3457.95,1836.32 3457.95,1871.75 3474.07,1887.87 U1.R8@3474.07,1889.56
  Signal Layer 3 w4.9: v1(2607.31,1777.88) 2607.31,1743.13 2616.54,1733.9 3411.71,1733.9 3455.84,1778.03 3455.84,1788.27 v2(3457.83,1790.27)
  Bottom w4.9: C132.1@2630.06,1839.38 2630.06,1816.17 2607.31,1793.42 v1(2607.31,1777.88) 2607.31,1742.36 2631.04,1718.63 R184.1@2631.04,1695.94
MCU_A10A11_P: C144.1 R183.1 U1.T8 | length 1227.9
  Top Layer w4.9: v2(3470.56,1770.91) 3472.1,1772.45 3472.1,1782.69 3479,1789.59 3479,1830.69 3468.85,1840.84 3468.85,1849.91 3474.07,1855.13 U1.T8@3474.07,1858.07
  Signal Layer 3 w4.9: v1(2591.31,1802.88) 2589.31,1800.88 2589.31,1745.72 2596.41,1738.62 2612.03,1723 3416.22,1723 3461.62,1768.4 3468.06,1768.4 v2(3470.56,1770.91)
  Bottom w4.9: R183.1@2567.96,1695.32 2567.96,1746.07 2588.31,1766.42 2588.31,1799.88 v1(2591.31,1802.88) 2591.31,1815.06 C144.1@2567.99,1838.38
MCU_A14B14C14A15B15C15_N: C133.1 R186.1 U1.R2 | length 1664.5
  Top Layer w4.9: C133.1@2382.06,1839.38 2382.06,1816.69 2369,1803.63 v1(2369,1743) 2369,1731.8 2382.67,1718.13 R186.1@2382.67,1695.94
  Top Layer w5: U1.R2@3285.09,1889.56 v2(3300.84,1873.81)
  Signal Layer 6 w4.9: v1(2369,1743) 2346.7,1720.7 2346.7,1703.3 2356,1694 2861.8,1694 2895.57,1727.77 3349.76,1727.77 3349.81,1727.72 3478.17,1727.72 3488,1737.55 3488,1785.68 3395.32,1878.36 3308.94,1878.36 3304.39,1873.81 v2(3300.84,1873.81)
MCU_A14B14C14A15B15C15_P: C145.1 R185.1 U1.R1 | length 1759.7
  Top Layer w4.9: C145.1@2320.06,1839.38 2320.06,1761.06 v1(2318,1759) 2320.58,1756.42 R185.1@2320.58,1695.94
  Top Layer w5: U1.R1@3253.6,1889.56 v2(3269.35,1873.81)
  Signal Layer 6 w4.9: v1(2318,1759) 2318,1742 2335.8,1724.2 2335.8,1698.79 2351.49,1683.1 2866.31,1683.1 2900.08,1716.87 3345.25,1716.87 3345.3,1716.82 3482.68,1716.82 3498.9,1733.03 3498.9,1790.2 3399.84,1889.26 3284.8,1889.26 v2(3269.35,1873.81)
MCU_B0B1_N: C134.1 R189.1 U1.T3 | length 1580.4
  Top Layer w5: v2(3300.84,1842.32) U1.T3@3316.59,1858.07
  Signal Layer 3 w5: v1(1990.06,1768.88) 1992.05,1770.86 1992.05,1783.05 2080.77,1871.77 3032.08,1871.77 3093.78,1810.07 3268.59,1810.07 v2(3300.84,1842.32)
  Bottom w4.9: C134.1@2009.17,1838.38 2009.17,1815.69 1990.06,1796.59 v1(1990.06,1768.88) 1990.06,1738.69 2010.13,1718.63 R189.1@2010.13,1695.94
MCU_B0B1_P: C146.1 R188.1 U1.T2 | length 1561.7
  Top Layer w5: v2(3269.35,1842.32) U1.T2@3285.09,1858.07
  Signal Layer 3 w5: v1(1967.06,1787.88) 1970.32,1791.13 1972.09,1789.36 1982.8,1789.36 2076.21,1882.77 3036.64,1882.77 3098.34,1821.07 3253.85,1821.07 3269.35,1836.57 v2(3269.35,1842.32)
  Bottom w4.9: C146.1@1947.08,1838.38 1947.08,1815.69 1967.06,1795.71 v1(1967.06,1787.88) 1967.06,1737.66 1948.04,1718.63 R188.1@1948.04,1695.94
MCU_B2B3_N: C135.1 R191.1 U1.P3 | length 1547
  Top Layer w5: v2(3300.84,1905.31) U1.P3@3316.59,1921.06
  Signal Layer 3 w4.9: v1(2118.23,1789.7) 2121.01,1792.49 2131.74,1792.49 2179.25,1840 2792.51,1840 2873.51,1759 3061.12,1759 3097.02,1794.9 3289.49,1794.9 3316.29,1821.71 3316.29,1891.18 3302.16,1905.31 v2(3300.84,1905.31)
  Bottom w4.9: R191.1@2133.33,1695.32 2133.33,1718.01 2118.23,1733.11 v1(2118.23,1789.7) 2118.23,1800.57 2133.35,1815.69 C135.1@2133.35,1838.38
MCU_B2B3_P: C147.1 R190.1 U1.R3 | length 1596.6
  Top Layer w5: U1.R3@3316.59,1889.56 v2(3332.34,1905.31)
  Signal Layer 3 w4.9: v1(2093.23,1764.7) 2119.37,1764.7 2183.77,1829.1 2788,1829.1 2869,1748.1 3065.64,1748.1 3101.54,1784 3294,1784 3327.19,1817.19 3327.19,1896.62 3332.34,1901.77 v2(3332.34,1905.31)
  Bottom w4.9: R190.1@2071.23,1695.32 2071.23,1717.51 2093.23,1739.5 v1(2093.23,1764.7) 2093.23,1794.23 2071.26,1816.19 C147.1@2071.26,1838.38
MCU_B4B5_N: C136.1 R193.1 U1.N7 | length 1896.3
  Top Layer w5: v2(3426.83,1936.81) U1.N7@3442.57,1952.55
  Signal Layer 6 w4.9: v1(2238.06,1774.88) 2237.94,1774.88 2222.62,1759.55 2222.62,1681.56 2252.91,1651.27 2898.27,1651.27 2924.17,1677.17 3471.76,1677.17 3519.83,1725.24 3519.83,1790.38 3419.33,1890.88 3419.33,1890.95 3413.42,1896.87 3413.35,1896.87 3411.33,1898.89 3411.33,1921.31 v2(3426.83,1936.81)
  Bottom w4.9: R193.1@2257.51,1695.32 2224,1728.83 2224,1758.36 2238.06,1772.42 2238.06,1796.22 2257.53,1815.69 C136.1@2257.53,1838.38
MCU_B4B5_P: C148.1 R192.1 U1.P7 | length 1887.1
  Top Layer w5: v2(3426.83,1905.31) U1.P7@3442.57,1921.06
  Signal Layer 6 w4.9: v1(2210.06,1790.88) 2211.72,1789.22 2211.72,1677.04 2248.39,1640.37 2902.78,1640.37 2928.68,1666.27 3476.28,1666.27 3530.73,1720.72 3530.73,1794.9 3430.23,1895.4 3430.23,1895.47 3429.33,1896.37 3429.33,1902.8 v2(3426.83,1905.31)
  Bottom w4.9: R192.1@2195.42,1695.32 2210.06,1709.97 v1(2210.06,1790.88) 2210.06,1801.07 2195.44,1815.69 C148.1@2195.44,1838.38
MCU_C2C3_N: C137.1 R196.1 U1.L5 | length 1236.7
  Top Layer w4.9: C137.1@2505.88,1839.38 2502,1835.5 v1(2502,1794) 2501.4,1793.4 2501.4,1773 2506.85,1767.54 R196.1@2506.85,1695.94
  Top Layer w5: v2(3363.83,1999.8) U1.L5@3379.58,2015.55
  Signal Layer 6 w5: v1(2502,1794) 2479.64,1816.36 2479.64,1827.33 2501.31,1849 2838.86,1849 3057.04,2067.19 3199.94,2067.19 3282.83,1984.3 3348.33,1984.3 v2(3363.83,1999.8)
MCU_C2C3_P: C149.1 R195.1 U1.L4 | length 1231.2
  Top Layer w4.9: C149.1@2443.79,1839.38 2443.79,1807.04 v1(2429.63,1792.88) 2444.76,1777.74 R195.1@2444.76,1695.94
  Top Layer w5: v2(3332.34,1999.8) U1.L4@3348.09,2015.55
  Signal Layer 6 w5: v1(2429.63,1792.88) 2496.75,1860 2833.59,1860 3049.22,2075.63 3049.93,2075.63 3052.48,2078.19 3204.5,2078.19 3263.66,2019.03 3313.11,2019.03 v2(3332.34,1999.8)
MCU_C4: C150.1 R197.1 U1.M6 | length 1519.7
  Top Layer w5: v2(3395.33,1968.3) U1.M6@3411.08,1984.05
  Signal Layer 6 w5: v1(2347,1794) 2446.77,1893.77 2827.6,1893.77 3070.6,2136.77 3234.35,2136.77 3291.46,2079.66 3368.89,2079.66 3379.33,2069.21 3379.33,1984.3 v2(3395.33,1968.3)
  Bottom w5: R197.1@2381.69,1695.32 2381.69,1719.69 2394.5,1732.5 2394.5,1755.42 2359.17,1790.75 2350.25,1790.75 v1(2347,1794) 2367.12,1814.12 2367.12,1823.79 C150.1@2381.72,1838.38
MCU_C6: C138.1 R201.1 U1.K5 | length 1403.4
  Top Layer w5: v2(3363.83,2031.29) U1.K5@3379.58,2047.04
  Signal Layer 6 w5: v1(2349.45,1767) 2467.22,1884.77 2833.58,1884.77 3076.58,2127.77 3230.62,2127.77 3287.73,2070.66 3326.09,2070.66 3363.83,2032.92 v2(3363.83,2031.29)
  Bottom w5: R201.1@2319.6,1695.32 2319.6,1696.31 2335.8,1712.51 2335.8,1714.37 2336.86,1715.44 2336.86,1754.41 v1(2349.45,1767) 2346.88,1769.57 2335.86,1769.57 2317,1788.44 2317,1835.76 C138.1@2319.62,1838.38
